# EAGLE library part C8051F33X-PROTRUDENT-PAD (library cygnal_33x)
Cygnal C8051F330/1 microcontroller with protrudent pad (for hand soldering)
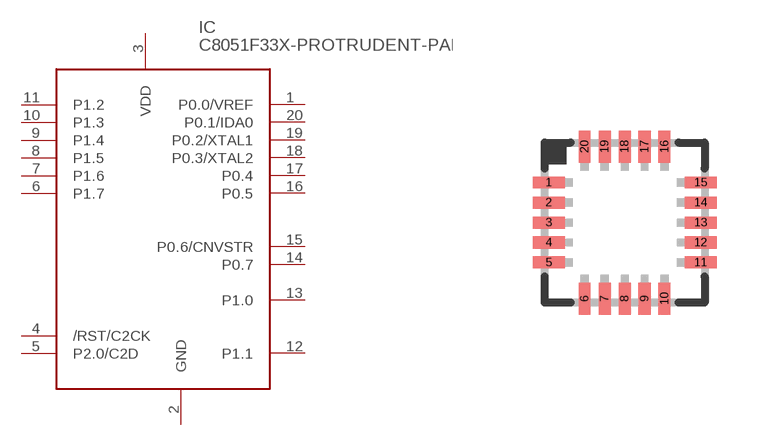
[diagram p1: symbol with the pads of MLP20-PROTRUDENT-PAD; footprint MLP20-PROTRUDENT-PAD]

Designator prefix IC

## C8051F33X-PROTRUDENT-PAD  [MLP20-PROTRUDENT-PAD]
1  P0.0/VREF  pas
2  GND  pwr
3  VDD  pwr
4  /RST/C2CK  pas
5  P2.0/C2D  pas
6  P1.7  pas
7  P1.6  pas
8  P1.5  pas
9  P1.4  pas
10  P1.3  pas
11  P1.2  pas
12  P1.1  pas
13  P1.0  pas
14  P0.7  pas
15  P0.6/CNVSTR  pas
16  P0.5  pas
17  P0.4  pas
18  P0.3/XTAL2  pas
19  P0.2/XTAL1  pas
20  P0.1/IDA0  pas

## Footprint MLP20-PROTRUDENT-PAD (pad centres in mm)
smd 0.8 x 0.3: 1 -1.9,1; 2 -1.9,0.5; 3 -1.9,0; 4 -1.9,-0.5; 5 -1.9,-1; 11 1.9,-1; 12 1.9,-0.5; 13 1.9,0; 14 1.9,0.5; 15 1.9,1
smd 0.3 x 0.8: 6 -1,-1.9; 7 -0.5,-1.9; 8 0,-1.9; 9 0.5,-1.9; 10 1,-1.9; 16 1,1.9; 17 0.5,1.9; 18 0,1.9; 19 -0.5,1.9; 20 -1,1.9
